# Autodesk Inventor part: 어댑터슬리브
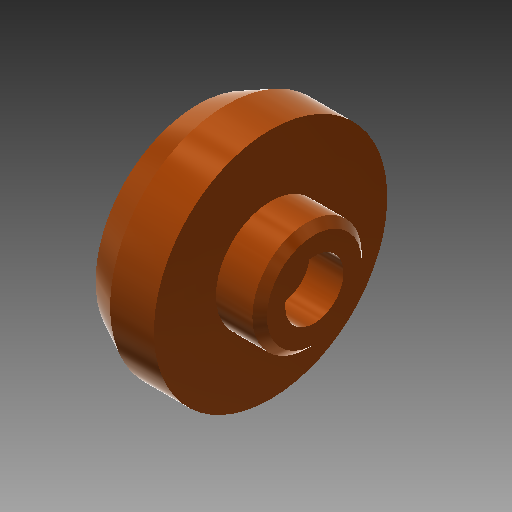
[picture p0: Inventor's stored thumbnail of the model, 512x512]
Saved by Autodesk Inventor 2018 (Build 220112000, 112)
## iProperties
Created: 2016-06
Part Number: 어댑터슬리브
Material: 강철, 탄소
Document SubType Name: Modeling
Designer: mduedu
Density: 7.87 g/cm^3
Appearance: 매끄러움 - 연한 주황색
Author: mduedu
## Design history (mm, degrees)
sketch "스케치2"
  geometry: L1 (0, 0)-(0, 14); L2 (0, 14)-(-4, 16); L3 (-4, 16)-(-10, 16); L4 (-10, 16)-(-10, 7.5); L5 (-10, 7.5)-(-16, 7.5); L6 (-16, 7.5)-(-16, 0); L7 (-16, 0)-(0, 0)
  constraints: 14 end point, 4 parallel, 1 perpendicular, 1 vertical
  dimensions: "d0" = 32 diameter of L3 L7; "d2" = 28 diameter of L1.end L7; "d3" = 6 distance of L2.end L3.end; "d4" = 6 distance of L4.end L5.end; "d5" = 15 diameter of L5 L7; "d6" = 16 distance between parallel lines of L6 L1
revolve "회전1" sketch "스케치2" stored, may be unused: angle "d7" = 90 deg
sketch "스케치3"
  geometry: L1 (-16, -7.5)-(-16, 7.5) reference; L2 (-16, 7.5)-(-10, 7.5) reference; L3 (-10, 7.5)-(-10, 16) reference; L4 (-10, 16)-(-4, 16) reference; L5 (-4, 16)-(0, 14) reference; L6 (0, 14)-(0, -14) reference; L7 (0, -14)-(-4, -16) reference; L8 (-4, -16)-(-10, -16) reference; L9 (-10, -16)-(-10, -7.5) reference; L10 (-10, -7.5)-(-16, -7.5) reference; L11 (0, 10)-(-5, 10); L12 (-5, 10)-(-5, 8); L13 (-5, 8)-(-7, 6); L14 (-7, 6)-(-7, 0); L15 (-7, 0)-(0, 0); L16 (0, 10)-(0, 0)
  constraints: 12 end point, 3 parallel, 2 perpendicular, 1 point on line
  dimensions: "d8" = 20 diameter of L11 L15; "d10" = 16 diameter of L12.end L15; "d11" = 12 diameter of L13.end L15; "d12" = 9 distance between parallel lines of L14 L1; "d13" = 2 distance between parallel lines of L12 L14
revolve "회전2" sketch "스케치3" stored, may be unused: angle "d14" = 90 deg
chamfer "모따기1" distance "d15" = 1; stored, may be unused: second distance "d16" = 2, angle "d17" = 45 deg
sketch "스케치4"
  geometry: 2 further points
  constraints: 1 coincident
sketch "스케치5"
  geometry: 1 further point
hole "구멍1" sketch "스케치5" at (0, 0) diameter "d18" = 4.5; stored, may be unused: countersink angle "d22" = 90 deg, drill point angle "d24" = 0 deg; dims "d19" = 6, "d20" = 8, "d21" = 4.6, "d23" = 8
node "솔리드1"
node "절단 모서리 투영1"
